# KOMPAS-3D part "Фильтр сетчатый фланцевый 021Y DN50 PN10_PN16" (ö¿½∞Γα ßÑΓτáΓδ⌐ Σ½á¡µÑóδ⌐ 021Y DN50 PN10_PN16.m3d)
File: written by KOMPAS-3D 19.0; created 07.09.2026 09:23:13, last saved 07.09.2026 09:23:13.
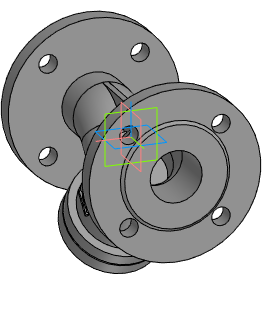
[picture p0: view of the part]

Document properties: Автор: Энергия; Полное имя файла: Z:\3.Личные\sachek\Dendor\_3D для проектировщиков\8.3 Фильтр сетчатый 021Y\021Y_STP\Фильтр сетчатый фланцевый 021Y DN50 PN10_PN16.m3d

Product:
- Part/product: Фильтр сетчатый фланцевый 021Y DN50 PN10_PN16

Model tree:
1. Операция без истории:1  (labels: Фильтр сетчатый фланцевый 021Y DN50 PN10_PN16)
